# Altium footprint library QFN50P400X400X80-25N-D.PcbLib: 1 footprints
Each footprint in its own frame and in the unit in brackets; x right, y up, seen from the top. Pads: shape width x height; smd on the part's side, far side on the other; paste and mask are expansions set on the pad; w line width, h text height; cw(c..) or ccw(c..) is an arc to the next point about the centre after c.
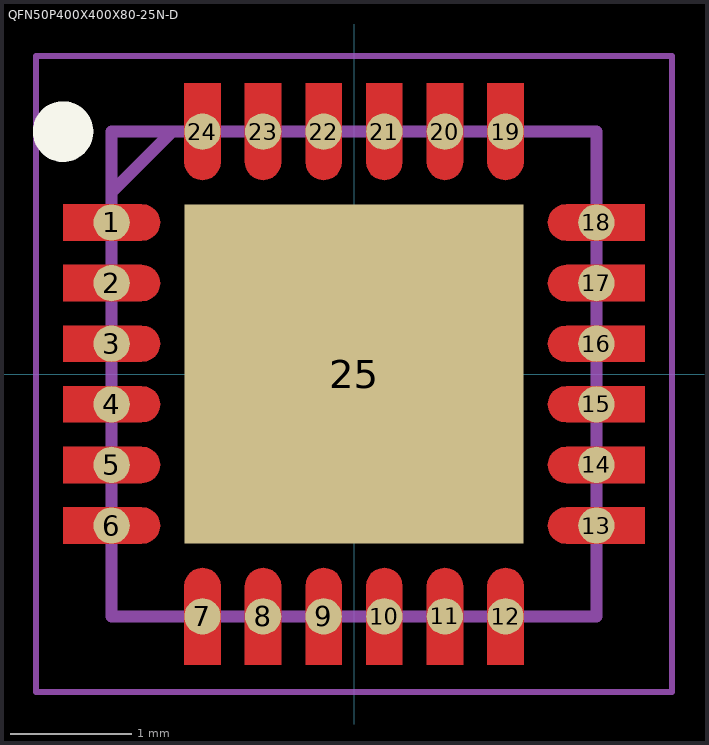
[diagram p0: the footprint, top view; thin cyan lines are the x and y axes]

## QFN50P400X400X80-25N-D [mm]
pads (25):
  round 0.3 smd: 1(-2,1.25) 2(-2,0.75) 3(-2,0.25) 4(-2,-0.25) 5(-2,-0.75) 6(-2,-1.25) 7(-1.25,-2) 8(-0.75,-2) 9(-0.25,-2) 10(0.25,-2) 11(0.75,-2) 12(1.25,-2) 13(2,-1.25) 14(2,-0.75) 15(2,-0.25) 16(2,0.25) 17(2,0.75) 18(2,1.25) 19(1.25,2) 20(0.75,2) 21(0.25,2) 22(-0.25,2) 23(-0.75,2) 24(-1.25,2)
  rect 2.8x2.8 smd: 25(0,0)
L1-Top Layer:
  region: -2.4,1.4 -1.75,1.4 -1.711,1.395 -1.675,1.38 -1.644,1.356 -1.62,1.325 -1.605,1.289 -1.6,1.25 -1.605,1.211 -1.62,1.175 -1.644,1.144 -1.675,1.12 -1.711,1.105 -1.75,1.1 -2.4,1.1
  region: -2.4,0.9 -1.75,0.9 -1.711,0.895 -1.675,0.88 -1.644,0.856 -1.62,0.825 -1.605,0.789 -1.6,0.75 -1.605,0.711 -1.62,0.675 -1.644,0.644 -1.675,0.62 -1.711,0.605 -1.75,0.6 -2.4,0.6
  region: -2.4,0.4 -1.75,0.4 -1.711,0.395 -1.675,0.38 -1.644,0.356 -1.62,0.325 -1.605,0.289 -1.6,0.25 -1.605,0.211 -1.62,0.175 -1.644,0.144 -1.675,0.12 -1.711,0.105 -1.75,0.1 -2.4,0.1
  region: -2.4,-0.1 -1.75,-0.1 -1.711,-0.105 -1.675,-0.12 -1.644,-0.144 -1.62,-0.175 -1.605,-0.211 -1.6,-0.25 -1.605,-0.289 -1.62,-0.325 -1.644,-0.356 -1.675,-0.38 -1.711,-0.395 -1.75,-0.4 -2.4,-0.4
  region: -2.4,-0.6 -1.75,-0.6 -1.711,-0.605 -1.675,-0.62 -1.644,-0.644 -1.62,-0.675 -1.605,-0.711 -1.6,-0.75 -1.605,-0.789 -1.62,-0.825 -1.644,-0.856 -1.675,-0.88 -1.711,-0.895 -1.75,-0.9 -2.4,-0.9
  region: -2.4,-1.1 -1.75,-1.1 -1.711,-1.105 -1.675,-1.12 -1.644,-1.144 -1.62,-1.175 -1.605,-1.211 -1.6,-1.25 -1.605,-1.289 -1.62,-1.325 -1.644,-1.356 -1.675,-1.38 -1.711,-1.395 -1.75,-1.4 -2.4,-1.4
  region: -1.4,-2.4 -1.4,-1.75 -1.395,-1.711 -1.38,-1.675 -1.356,-1.644 -1.325,-1.62 -1.289,-1.605 -1.25,-1.6 -1.211,-1.605 -1.175,-1.62 -1.144,-1.644 -1.12,-1.675 -1.105,-1.711 -1.1,-1.75 -1.1,-2.4
  region: -0.9,-2.4 -0.9,-1.75 -0.895,-1.711 -0.88,-1.675 -0.856,-1.644 -0.825,-1.62 -0.789,-1.605 -0.75,-1.6 -0.711,-1.605 -0.675,-1.62 -0.644,-1.644 -0.62,-1.675 -0.605,-1.711 -0.6,-1.75 -0.6,-2.4
  region: -0.4,-2.4 -0.4,-1.75 -0.395,-1.711 -0.38,-1.675 -0.356,-1.644 -0.325,-1.62 -0.289,-1.605 -0.25,-1.6 -0.211,-1.605 -0.175,-1.62 -0.144,-1.644 -0.12,-1.675 -0.105,-1.711 -0.1,-1.75 -0.1,-2.4
  region: 0.1,-2.4 0.1,-1.75 0.105,-1.711 0.12,-1.675 0.144,-1.644 0.175,-1.62 0.211,-1.605 0.25,-1.6 0.289,-1.605 0.325,-1.62 0.356,-1.644 0.38,-1.675 0.395,-1.711 0.4,-1.75 0.4,-2.4
  region: 0.6,-2.4 0.6,-1.75 0.605,-1.711 0.62,-1.675 0.644,-1.644 0.675,-1.62 0.711,-1.605 0.75,-1.6 0.789,-1.605 0.825,-1.62 0.856,-1.644 0.88,-1.675 0.895,-1.711 0.9,-1.75 0.9,-2.4
  region: 1.1,-2.4 1.1,-1.75 1.105,-1.711 1.12,-1.675 1.144,-1.644 1.175,-1.62 1.211,-1.605 1.25,-1.6 1.289,-1.605 1.325,-1.62 1.356,-1.644 1.38,-1.675 1.395,-1.711 1.4,-1.75 1.4,-2.4
  region: 2.4,-1.4 1.75,-1.4 1.711,-1.395 1.675,-1.38 1.644,-1.356 1.62,-1.325 1.605,-1.289 1.6,-1.25 1.605,-1.211 1.62,-1.175 1.644,-1.144 1.675,-1.12 1.711,-1.105 1.75,-1.1 2.4,-1.1
  region: 2.4,-0.9 1.75,-0.9 1.711,-0.895 1.675,-0.88 1.644,-0.856 1.62,-0.825 1.605,-0.789 1.6,-0.75 1.605,-0.711 1.62,-0.675 1.644,-0.644 1.675,-0.62 1.711,-0.605 1.75,-0.6 2.4,-0.6
  region: 2.4,-0.4 1.75,-0.4 1.711,-0.395 1.675,-0.38 1.644,-0.356 1.62,-0.325 1.605,-0.289 1.6,-0.25 1.605,-0.211 1.62,-0.175 1.644,-0.144 1.675,-0.12 1.711,-0.105 1.75,-0.1 2.4,-0.1
  region: 2.4,0.1 1.75,0.1 1.711,0.105 1.675,0.12 1.644,0.144 1.62,0.175 1.605,0.211 1.6,0.25 1.605,0.289 1.62,0.325 1.644,0.356 1.675,0.38 1.711,0.395 1.75,0.4 2.4,0.4
  region: 2.4,0.6 1.75,0.6 1.711,0.605 1.675,0.62 1.644,0.644 1.62,0.675 1.605,0.711 1.6,0.75 1.605,0.789 1.62,0.825 1.644,0.856 1.675,0.88 1.711,0.895 1.75,0.9 2.4,0.9
  region: 2.4,1.1 1.75,1.1 1.711,1.105 1.675,1.12 1.644,1.144 1.62,1.175 1.605,1.211 1.6,1.25 1.605,1.289 1.62,1.325 1.644,1.356 1.675,1.38 1.711,1.395 1.75,1.4 2.4,1.4
  region: 1.4,2.4 1.4,1.75 1.395,1.711 1.38,1.675 1.356,1.644 1.325,1.62 1.289,1.605 1.25,1.6 1.211,1.605 1.175,1.62 1.144,1.644 1.12,1.675 1.105,1.711 1.1,1.75 1.1,2.4
  region: 0.9,2.4 0.9,1.75 0.895,1.711 0.88,1.675 0.856,1.644 0.825,1.62 0.789,1.605 0.75,1.6 0.711,1.605 0.675,1.62 0.644,1.644 0.62,1.675 0.605,1.711 0.6,1.75 0.6,2.4
  region: 0.4,2.4 0.4,1.75 0.395,1.711 0.38,1.675 0.356,1.644 0.325,1.62 0.289,1.605 0.25,1.6 0.211,1.605 0.175,1.62 0.144,1.644 0.12,1.675 0.105,1.711 0.1,1.75 0.1,2.4
  region: -0.1,2.4 -0.1,1.75 -0.105,1.711 -0.12,1.675 -0.144,1.644 -0.175,1.62 -0.211,1.605 -0.25,1.6 -0.289,1.605 -0.325,1.62 -0.356,1.644 -0.38,1.675 -0.395,1.711 -0.4,1.75 -0.4,2.4
  region: -0.6,2.4 -0.6,1.75 -0.605,1.711 -0.62,1.675 -0.644,1.644 -0.675,1.62 -0.711,1.605 -0.75,1.6 -0.789,1.605 -0.825,1.62 -0.856,1.644 -0.88,1.675 -0.895,1.711 -0.9,1.75 -0.9,2.4
  region: -1.1,2.4 -1.1,1.75 -1.105,1.711 -1.12,1.675 -1.144,1.644 -1.175,1.62 -1.211,1.605 -1.25,1.6 -1.289,1.605 -1.325,1.62 -1.356,1.644 -1.38,1.675 -1.395,1.711 -1.4,1.75 -1.4,2.4
Top Overlay:
  circle w0.25: c-2.4,2 r0.125
Mechanical 15:
  lines w0.1: -2,1.5 -1.5,2 ; -2,-2 2,-2 2,2 -2,2 -2,-2
Mechanical 20:
  lines w0.05: -2.625,-2.625 2.625,-2.625 2.625,2.625 -2.625,2.625 -2.625,-2.625
3D body "IS31FL3728-QFLS2-TR.stp": height 5.8, standoff -4.65, extent -10,-3.376 10,3.376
